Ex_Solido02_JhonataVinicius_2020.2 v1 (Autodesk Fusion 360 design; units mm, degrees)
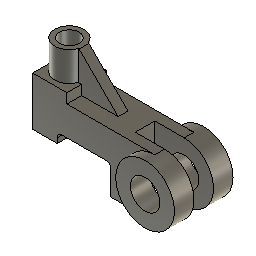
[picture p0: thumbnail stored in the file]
sketch "Sketch1" plane through (0, 0, 0) normal (0, 1, 0) x axis (1, 0, 0)
  line L1 (-50, 25) -> (-50, -25)
  line L2 (-25, 25) -> (-50, 25)
  line L3 (-25, 15) -> (-25, 25)
  line L4 (30, 15) -> (-25, 15)
  line L5 (30, 45) -> (30, 15)
  line L6 (75, 45) -> (30, 45)
  line L7 (-15, -25) -> (-50, -25)
  line L8 (-15, -15) -> (-15, -25)
  line L9 (75, -15) -> (-15, -15)
  line L10 (105, 15) -> (50, 15)
  line L11 (75, 55) -> (75, -25)
  circle C1 centre (75, 15) radius 30
  circle C2 centre (75, 15) radius 15
  point P11 (75, -15)
  point P14 (75, 15)
  point P9 (-15, -25)
  point P10 (-15, -15)
  point P6 (30, 15)
  point P7 (30, 45)
  vertical L1
  perpendicular L1 L2
  perpendicular L2 L3
  perpendicular L3 L4
  perpendicular L4 L5
  perpendicular L3 L6
  perpendicular L1 L7
  perpendicular L7 L8
  perpendicular L8 L9
  horizontal L10
  coincident P11 C1
  concentric C1 C2
  vertical L11
  coincident P14 L11
  dimension "d1" distance L2 L7 = 50
  dimension "d2" distance L1 L3 = 25
  dimension "d3" distance L3 L5 = 55
  dimension "d6" distance L4 L9 = 30
  dimension "d7" distance L1 L8 = 35
  dimension "d8" distance P9 P10 = 10
  dimension "d9" distance P6 P7 = 30
  dimension "d10" distance L9 L10 = 30
  dimension "d11" diameter C2 = 30
  dimension "d12" distance L5 L11 = 45
extrude "Extrude1" new body sketch "Sketch1" profile of L1 L2 L3 L4 L5 L6 L7 L8 L9 C1 along normal blind 40
extrude "Extrude2" add sketch "Sketch1" profile of C1 C2 along normal blind 50 and against normal blind 10
sketch "Sketch2" plane through (0, 0, 15) normal (0, 0, 1) x axis (-1, 0, 0)
  line L1 (-75, 0) -> (15, 0)
  line L2 (-75, -40) -> (-75, 0)
  line L3 (15, -40) -> (-75, -40)
  line L4 (15, 0) -> (15, -40)
  line L5 (-139.7446, -10) -> (-45, -10)
  line L6 (-139.7446, -30) -> (-139.7446, -10)
  line L7 (-45, -30) -> (-139.7446, -30)
  line L8 (-45, -10) -> (-45, -30)
  horizontal L5
  vertical L6
  horizontal L7
  vertical L8
  dimension "d19" distance L5 L7 = 20
  dimension "d20" distance L1 L5 = 10
  dimension "d21" distance L2 L8 = 30
extrude "Extrude3" cut sketch "Sketch2" profile of L2 L5 L6 L7 L8 against normal blind 60
sketch "Sketch3" plane through (0, 0, 25) normal (0, 0, 1) x axis (-1, 0, 0)
  line L1 (15, 0) -> (50, 0)
  line L2 (15, -40) -> (15, 0)
  line L3 (50, -40) -> (15, -40)
  line L4 (50, 0) -> (50, -40)
  line L5 (50, 0) -> (15, -40)
  line L6 (15, 0) -> (50, -40)
  circle C1 centre (32.5, -20) radius 15
  circle C2 centre (32.5, -20) radius 10
  point P4 (15, -40)
  point P6 (15, -40)
  point P2 (50, 0)
  point P7 (50, 0)
  point P5 (50, -40)
  point P8 (50, -40)
  point P3 (15, 0)
  point P9 (15, 0)
  point P10 (32.5, -20)
  coincident P4 P6
  coincident P2 P7
  coincident P5 P8
  coincident P3 P9
  midpoint L5 P10
  concentric C1 C2
  dimension "d24" diameter C1 = 30
  dimension "d25" diameter C2 = 20
extrude "Extrude4" add sketch "Sketch3" profile of C1 C2 along normal blind 30
work_plane "WorkPlane1"
sketch "Sketch4" plane through (12.5, 20, -10) normal (0, -1, 0) x axis (1, 0, 0)
  line L1 (-33, 25) -> (-33, 65)
  line L2 (10, 25) -> (-33, 25)
  line L3 (-30, 65) -> (10, 25)
  line L4 (-33, 65) -> (-30, 65)
  point P2 (-33, 65)
  point P5 (-30, 65)
  point P3 (-33, 25)
  point P4 (10, 25)
  vertical L1
  perpendicular L1 L2
  perpendicular L1 L4
  dimension "d28" distance P2 P5 = 3
  dimension "d29" distance P2 P3 = 40
  dimension "d30" distance P3 P4 = 43
extrude "Extrude5" add sketch "Sketch4" distance 5
fillet "Fillet1" radius 5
